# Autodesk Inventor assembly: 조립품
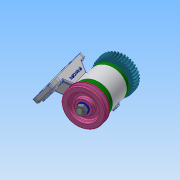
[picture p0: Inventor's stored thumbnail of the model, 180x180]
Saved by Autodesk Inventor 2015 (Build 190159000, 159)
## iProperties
Created: 2023-08
Part Number: 조립품
Document SubType Name: Assembly
Designer: 학생용
Author: 학생용
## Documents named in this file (12)
- C:\Users\학생용\Desktop\730806V1010\조립품.iam
- C:\Users\학생용\Desktop\730806V1010\V벨트풀리.ipt
- C:\Users\학생용\Desktop\730806V1010\너트 M12x1.25.ipt
- C:\Users\학생용\Desktop\730806V1010\베어링 6204.ipt
- C:\Users\학생용\Desktop\730806V1010\본체.ipt
- C:\Users\학생용\Desktop\730806V1010\볼트 M4 x 12.ipt
- C:\Users\학생용\Desktop\730806V1010\스퍼기어.ipt
- C:\Users\학생용\Desktop\730806V1010\오일실 20x35x8.ipt
- C:\Users\학생용\Desktop\730806V1010\와셔 12x24.ipt
- C:\Users\학생용\Desktop\730806V1010\축.ipt
- C:\Users\학생용\Desktop\730806V1010\커버.ipt
- C:\Users\학생용\Desktop\730806V1010\키 5x5.ipt
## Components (1 placed, 1 different names)
1. V벨트풀리:1
